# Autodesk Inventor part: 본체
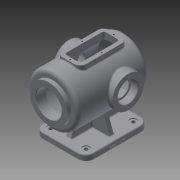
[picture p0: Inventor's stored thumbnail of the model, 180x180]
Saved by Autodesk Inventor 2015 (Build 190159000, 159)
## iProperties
Created: 2021-11
Part Number: 본체
Material: 일반
Document SubType Name: Modeling
Designer: G08
Density: 1 g/cm^3
Appearance: 기본값
Author: G08
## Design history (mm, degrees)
sketch "스케치1"
  geometry: L1 (65, -80)-(-65, -80); L2 (-65, -80)-(-65, 80); L3 (-65, 80)-(65, 80); L4 (65, 80)-(65, -80); L5 (65, -80)-(-65, 80); L6 (-65, -80)-(65, 80); 1 further point
  constraints: 12 end point, 2 midpoint, 2 parallel, 1 horizontal, 1 perpendicular
  dimensions: "d0" = 130 distance of L2.end L3.end; "d1" = 160 distance of L1.end L2.end
extrude "돌출1" new body sketch "스케치1" distance "d2" = 14; taper "d3" = 0 deg
sketch "스케치2"
  geometry: L1 (-65, 0)-(-65, 14) reference; L2 (-65, 14)-(65, 14) reference; L3 (65, 14)-(65, 0) reference; L4 (65, 0)-(-65, 0) reference; C1 r 65 at (0, 114); 1 further point
  constraints: 1 centre point
  dimensions: "d5" = 130 diameter of C1; "d6" = 114 distance from line of L4 C1.centre
extrude "돌출2" join sketch "스케치2" stored distance "d7" = 200; taper "d8" = 0 deg
sketch "스케치3"
  geometry: L1 (50, -7)-(-50, -7); L2 (-50, -7)-(-50, 7); L3 (-50, 7)-(50, 7); L4 (50, 7)-(50, -7); L5 (50, -7)-(-50, 7); L6 (-50, -7)-(50, 7); L7 (7, -60)-(-7, -60); L8 (-7, -60)-(-7, 60); L9 (-7, 60)-(7, 60); L10 (7, 60)-(7, -60); L11 (7, -60)-(-7, 60); L12 (-7, -60)-(7, 60); 1 further point
  constraints: 24 end point, 4 midpoint, 4 parallel, 2 horizontal, 2 perpendicular
  dimensions: "d9" = 14 distance of L8.end L9.end; "d10" = 14 distance of L3.end L1.start; "d11" = 120 distance of L9.end L7.start; "d12" = 100 distance of L2.end L3.end
extrude "돌출3" join sketch "스케치3" stored distance "d13" = 210; taper "d14" = 0 deg
sketch "스케치4"
  geometry: C1 r 65 at (0, 0) reference; C2 r 47.5 at (0, 0); 1 further point
  constraints: 1 centre point, 1 coincident
  dimensions: "d15" = 95 diameter of C2
extrude "돌출4" join sketch "스케치4" distance "d16" = 10; taper "d17" = 0 deg
sketch "스케치5"
  geometry: C1 r 47.5 at (0, 0) reference; 1 further point
hole "구멍1" sketch "스케치5" at (0, 0) diameter "d18" = 65; stored, may be unused: countersink angle "d22" = 90 deg, drill point angle "d24" = 0 deg; dims "d19" = 6, "d20" = 4, "d21" = 2, "d23" = 25
sketch "스케치6"
  geometry: C1 r 32.5 at (0, 0) reference; C2 r 55 at (0, 0); 1 further point
  constraints: 1 centre point, 1 coincident
  dimensions: "d25" = 110 diameter of C2
extrude "돌출5" cut sketch "스케치6" distance "d26" = 175; taper "d27" = 0 deg
sketch "스케치8"
  geometry: L1 (-80, 0)-(-80, 14) reference; L2 (-80, 14)-(-60, 14) reference; L3 (-60, 14)-(-60, 49) reference; L4 (-60, 49)-(-100, 49) reference; L5 (-100, 49)-(-100, 66.5) reference; L6 (-100, 66.5)-(-110, 66.5) reference; L7 (-110, 66.5)-(-110, 81.5) reference; L8 (-110, 81.5)-(-85, 81.5) reference; L9 (-85, 81.5)-(-85, 59) reference; L10 (-85, 59)-(90, 59) reference; L11 (90, 59)-(90, 169) reference; L12 (90, 169)-(-85, 169) reference; L13 (-85, 169)-(-85, 146.5) reference; L14 (-85, 146.5)-(-110, 146.5) reference; L15 (-110, 146.5)-(-110, 161.5) reference; L16 (-110, 161.5)-(-100, 161.5) reference; L17 (-100, 161.5)-(-100, 179) reference; L18 (-100, 179)-(100, 179) reference; L19 (100, 179)-(100, 49) reference; L20 (100, 49)-(60, 49) reference; L21 (60, 49)-(60, 14) reference; L22 (60, 14)-(80, 14) reference; L23 (80, 14)-(80, 0) reference; L24 (80, 0)-(-80, 0) reference; C1 r 21 at (17, 114); 1 further point
  constraints: 1 centre point
  dimensions: "d28" = 42 diameter of C1; "d29" = 127 distance from line of L15 C1.centre; "d30" = 114 distance from line of L24 C1.centre
extrude "돌출6" cut sketch "스케치8" stored distance "d31" = 175; taper "d32" = 0 deg
node "작업 평면3"
  node "작업 평면2"
sketch "스케치9"
  geometry: L1 (100, -65)-(100, 65) reference; L2 (-100, 65)-(-100, -65) reference; L3 (7, -41.533)-(-7, -41.533) reference; L4 (-7, -41.533)-(-7, -64.622) reference; L5 (-7, -64.622)-(-60, -64.622) reference; L6 (-60, -64.622)-(-60, -64.622) reference; L7 (-60, -64.622)-(-7, -64.622) reference; L8 (-7, -64.622)-(-7, -41.533) reference; L9 (-7, -41.533)-(7, -41.533) reference; L10 (7, -41.533)-(7, -64.622) reference; L11 (7, -64.622)-(60, -64.622) reference; L12 (60, -64.622)-(60, -64.622) reference; L13 (60, -64.622)-(7, -64.622) reference; L14 (7, -64.622)-(7, -41.533) reference; L15 (-80, -114)-(80, -114) reference; L16 (-80, -114)-(80, -114) reference; L17 (-80, -114)-(-80, -100) reference; L18 (80, -100)-(-80, -100) reference; L19 (80, -114)-(80, -100) reference; L20 (-110, 47.5)-(-110, -47.5) reference; C1 r 40 at (17, 0); 3 further points
  constraints: 1 centre point, 2 other
  dimensions: "d34" = 80 diameter of C1; "d35" = 114 distance from line of L15 C1.centre; "d36" = 127 distance from line of L20 C1.centre
extrude "돌출7" join sketch "스케치9" stored distance "d37" = 175; taper "d38" = 0 deg
sketch "스케치10"
  geometry: C1 r 40 at (0, 0) reference; C2 r 26 at (0, 0); 2 further points
  constraints: 1 centre point, 1 coincident, 1 other
  dimensions: "d39" = 52 diameter of C2
extrude "돌출8" cut sketch "스케치10" distance "d40" = 18; taper "d41" = 0 deg
node "작업 평면5"
  node "작업 평면4"
sketch "스케치11"
  geometry: L1 (-55, -85)-(-55, 90) reference; L2 (-65, -100)-(65, -100) reference; L3 (65, 100)-(-65, 100) reference; L4 (-47.5, -110)-(47.5, -110) reference; L5 (-65, -100)-(-65, 100) reference; L6 (65, -100)-(65, 100) reference; L7 (55, -85)-(55, 90) reference; L8 (30, -60)-(-30, -60); L9 (-30, -60)-(-30, 60); L10 (-30, 60)-(30, 60); L11 (30, 60)-(30, -60); L12 (30, -60)-(-30, 60); L13 (-30, -60)-(30, 60); L14 (75, 57)-(75, -23) reference; 2 further points
  constraints: 12 end point, 2 midpoint, 2 parallel, 1 horizontal, 1 perpendicular
  dimensions: "d43" = 60 distance of L9.end L10.end; "d44" = 120 distance of L8.end L9.end; "d45" = 50 distance between parallel lines of L4 L8; "d46" = 45 distance between parallel lines of L14 L11
extrude "돌출9" join sketch "스케치11" stored distance "d47" = 18; taper "d48" = 0 deg
sketch "스케치12"
  geometry: L1 (20, -50)-(-20, -50); L2 (-20, -50)-(-20, 50); L3 (-20, 50)-(20, 50); L4 (20, 50)-(20, -50); L5 (20, -50)-(-20, 50); L6 (-20, -50)-(20, 50); 1 further point
  constraints: 12 end point, 2 midpoint, 2 parallel, 1 horizontal, 1 perpendicular
  dimensions: "d49" = 40 distance of L2.end L3.end; "d50" = 100 distance of L1.end L2.end
extrude "돌출10" cut sketch "스케치12" distance "d51" = 30; taper "d52" = 0 deg
fillet "모깎기1" dims "d53" = 15
fillet "모깎기2" dims "d54" = 5
sketch "스케치13"
  geometry: 5 further points
  constraints: 2 horizontal alignment, 2 vertical alignment
  dimensions: "d55" = 25 distance of point (0, 0) point (-25, 0); "d56" = 50 distance of point (-25, 0) point (25, 0); "d57" = 110 distance of point (0, 55) point (0, -55); "d58" = 55 distance of point (0, 0) point (0, -55)
hole "구멍2" sketch "스케치13" at (-25, 0), (25, 0), (0, 55), (0, -55) diameter "d59" = 3.242; stored, may be unused: countersink angle "d63" = 90 deg, drill point angle "d65" = 118 deg; dims "d60" = 9, "d61" = 4, "d62" = 2, "d64" = 11
sketch "스케치14"
  geometry: L1 (0, 160)-(0, 0) reference; L2 (-31.658, 74.061)-(-31.658, 85.939); L3 (-31.658, 85.939)-(21.658, 85.939); L4 (21.658, 85.939)-(21.658, 74.061); L5 (21.658, 74.061)-(-31.658, 74.061); 2 further points
  constraints: 1 midpoint, 2 other
feature "엠보싱1" sketch "스케치14" dims "d68" = 0.5, "d69" = 0
sketch "스케치15"
  geometry: C1 r 26 at (0, 0) reference; 2 further points
  constraints: 1 horizontal alignment
  dimensions: "d70" = 32.5 distance of C1.centre point (-32.5, 0)
hole "구멍3" sketch "스케치15" at (-32.5, 0) diameter "d71" = 3.242; stored, may be unused: countersink angle "d75" = 90 deg, drill point angle "d77" = 118 deg; dims "d72" = 11, "d73" = 4, "d74" = 2, "d76" = 13
sketch "스케치16"
  geometry: C1 r 32.5 at (0, 0) reference; 2 further points
  constraints: 1 vertical alignment
  dimensions: "d81" = 40 distance of C1.centre point (0, 40)
hole "구멍4" sketch "스케치16" at (0, 40) diameter "d82" = 3.242; stored, may be unused: countersink angle "d86" = 90 deg, drill point angle "d88" = 118 deg; dims "d83" = 11, "d84" = 4, "d85" = 2, "d87" = 13
fillet "모깎기3" dims "d92" = 3
fillet "모깎기4" dims "d93" = 20
fillet "모깎기5" dims "d94" = 3
fillet "모깎기6" dims "d95" = 10
feature "면 기울기1" dims angle "d96" = 20 deg
feature "면 기울기2" dims angle "d97" = 20 deg
sketch "스케치18"
  geometry: C1 r 55 at (0, 0) reference; 1 further point
extrude "돌출11" join sketch "스케치18" distance "d100" = 20; taper "d101" = 0 deg
sketch "스케치17"
  geometry: L1 (-50, 184)-(-50, 169) reference; L2 (-50, 169)-(-85, 169) reference; L3 (-85, 81.5)-(-85, 59) reference; L4 (-110, 81.5)-(-85, 81.5) reference; L5 (-110, 146.5)-(-110, 152.379) reference; L6 (-110, 152.379)-(-97, 152.379) reference; L7 (-97, 152.379)-(-96.026, 154) reference; L8 (-96.026, 154)-(-97, 155.621) reference; L9 (-97, 155.621)-(-110, 155.621) reference; L10 (-110, 155.621)-(-110, 161.5) reference; L11 (-100, 66.5)-(-110, 66.5) reference; L12 (-100, 59)-(-100, 66.5) reference; L13 (-90, 179)-(-63, 179) reference; L14 (-60, 182)-(-60, 184) reference; L15 (-60, 184)-(-56.621, 184) reference; L16 (-56.621, 184)-(-56.621, 173) reference; L17 (-56.621, 173)-(-55, 172.026) reference; L18 (-55, 172.026)-(-53.379, 173) reference; L19 (-53.379, 173)-(-53.379, 184) reference; L20 (-53.379, 184)-(-50, 184) reference; L21 (70, 169)-(50, 169) reference; L22 (50, 169)-(50, 184) reference; L23 (50, 184)-(53.379, 184) reference; L24 (53.379, 184)-(53.379, 173) reference; L25 (53.379, 173)-(55, 172.026) reference; L26 (55, 172.026)-(56.621, 173) reference; L27 (56.621, 173)-(56.621, 184) reference; L28 (56.621, 184)-(60, 184) reference; L29 (60, 184)-(60, 182) reference; L30 (63, 179)-(100, 179) reference; L31 (100, 179)-(100, 49) reference; L32 (100, 49)-(47.261, 49) reference; L33 (47.261, 49)-(60, 14) reference; L34 (60, 14)-(77, 14) reference; L35 (80, 11)-(80, 0) reference; L36 (80, 0)-(-80, 0) reference; L37 (-80, 0)-(-80, 11) reference; L38 (-77, 14)-(-60, 14) reference; L39 (-60, 14)-(-47.261, 49) reference; L40 (-47.261, 49)-(-90, 49) reference; L41 (-100, 161.5)-(-100, 169) reference; L42 (-110, 161.5)-(-100, 161.5) reference; L43 (-110, 66.5)-(-110, 72.379) reference; L44 (-110, 72.379)-(-97, 72.379) reference; L45 (-97, 72.379)-(-96.026, 74) reference; L46 (-96.026, 74)-(-97, 75.621) reference; L47 (-97, 75.621)-(-110, 75.621) reference; L48 (-110, 75.621)-(-110, 81.5) reference; L49 (-85, 146.5)-(-110, 146.5) reference; L50 (-85, 169)-(-85, 146.5) reference; L51 (100, 49)-(100, 179) reference; L52 (100, 114)-(-110, 114); L53 (-85, 59)-(70, 59) reference; L54 (70, 59)-(70, 169) reference; A1 r 10 centre (-90, 59) between (-100, 59) and (-90, 49) reference; A2 r 3 centre (-63, 182) between (-63, 179) and (-60, 182) reference; A3 r 3 centre (63, 182) between (60, 182) and (63, 179) reference; A4 r 3 centre (77, 11) between (80, 11) and (77, 14) reference; A5 r 3 centre (-77, 11) between (-77, 14) and (-80, 11) reference; A6 r 10 centre (-90, 169) between (-90, 179) and (-100, 169) reference; A7 r 130.668 centre (0, 114) between (63.86, 0) and (79.982, 10.671); A8 r 100 centre (0, 114) between (100, 114) and (75.993, 179); 1 further point; 1 other entity
  constraints: 5 point on circle, 2 centre point, 2 end point, 2 point on line, 1 horizontal, 1 midpoint, 1 tangent, 2 other
  dimensions: "d99" = 100 radius of A8
revolve "회전1" sketch "스케치17" stored, may be unused: angle "d102" = 90 deg
sketch "스케치19"
  geometry: L1 (50, 169)-(50, 184) reference; L2 (50, 184)-(53.379, 184) reference; L3 (53.379, 184)-(53.379, 173) reference; L4 (53.379, 173)-(55, 172.026) reference; L5 (55, 172.026)-(56.621, 173) reference; L6 (56.621, 173)-(56.621, 184) reference; L7 (56.621, 184)-(60, 184) reference; L8 (60, 184)-(60, 182) reference; L9 (63, 179)-(75.993, 179) reference; L10 (75.993, 49)-(47.261, 49) reference; L11 (47.261, 49)-(60, 14) reference; L12 (60, 14)-(77, 14) reference; L13 (80, 11)-(80, 0) reference; L14 (80, 0)-(-80, 0) reference; L15 (-80, 0)-(-80, 11) reference; L16 (-77, 14)-(-60, 14) reference; L17 (-60, 14)-(-47.261, 49) reference; L18 (-47.261, 49)-(-90, 49) reference; L19 (-100, 59)-(-100, 66.5) reference; L20 (-100, 66.5)-(-110, 66.5) reference; L21 (-110, 66.5)-(-110, 72.379) reference; L22 (-110, 72.379)-(-97, 72.379) reference; L23 (-97, 72.379)-(-96.026, 74) reference; L24 (-96.026, 74)-(-97, 75.621) reference; L25 (-97, 75.621)-(-110, 75.621) reference; L26 (-110, 75.621)-(-110, 81.5) reference; L27 (-110, 81.5)-(-85, 81.5) reference; L28 (-85, 81.5)-(-85, 59) reference; L29 (-85, 59)-(70, 59) reference; L30 (70, 59)-(70, 169) reference; L31 (70, 169)-(50, 169) reference; L32 (-50, 184)-(-50, 169) reference; L33 (-50, 169)-(-85, 169) reference; L34 (-85, 169)-(-85, 146.5) reference; L35 (-85, 146.5)-(-110, 146.5) reference; L36 (-110, 146.5)-(-110, 152.379) reference; L37 (-110, 152.379)-(-97, 152.379) reference; L38 (-97, 152.379)-(-96.026, 154) reference; L39 (-96.026, 154)-(-97, 155.621) reference; L40 (-97, 155.621)-(-110, 155.621) reference; L41 (-110, 155.621)-(-110, 161.5) reference; L42 (-110, 161.5)-(-100, 161.5) reference; L43 (-100, 161.5)-(-100, 169) reference; L44 (-90, 179)-(-63, 179) reference; L45 (-60, 182)-(-60, 184) reference; L46 (-60, 184)-(-56.621, 184) reference; L47 (-56.621, 184)-(-56.621, 173) reference; L48 (-56.621, 173)-(-55, 172.026) reference; L49 (-55, 172.026)-(-53.379, 173) reference; L50 (-53.379, 173)-(-53.379, 184) reference; L51 (-53.379, 184)-(-50, 184) reference; L52 (0, 114)-(90, 114); L53 (45, 170.833)-(-45, 170.833) reference; L54 (0, 169)-(0, 114); L55 (71.239, 169)-(0, 169); A1 r 3 centre (63, 182) between (60, 182) and (63, 179) reference; A2 r 100 centre (0, 114) between (75.993, 49) and (75.993, 179) reference; A3 r 3 centre (77, 11) between (80, 11) and (77, 14) reference; A4 r 3 centre (-77, 11) between (-77, 14) and (-80, 11) reference; A5 r 10 centre (-90, 59) between (-100, 59) and (-90, 49) reference; A6 r 10 centre (-90, 169) between (-90, 179) and (-100, 169) reference; A7 r 3 centre (-63, 182) between (-63, 179) and (-60, 182) reference; A8 r 90 centre (0, 114) between (90, 114) and (71.239, 169); 3 further points
  constraints: 6 end point, 2 horizontal, 2 midpoint, 2 point on circle, 1 centre point, 1 point on line, 1 vertical
  dimensions: "d104" = 10 radial gap between concentric circles of A2 A8
revolve "회전2" sketch "스케치19" stored, may be unused: angle "d105" = 90 deg
fillet "모깎기7" dims "d106" = 10
fillet "모깎기8" dims "d107" = 3
fillet "모깎기9" dims "d108" = 3
chamfer "모따기1" distance "d109" = 1; stored, may be unused: second distance "d110" = 2, angle "d111" = 45 deg
fillet "모깎기10" dims "d112" = 3
fillet "모깎기11" dims "d113" = 3
sketch "스케치20"
  geometry: A1 r 17 centre (45, -60) between (45, -77) and (62, -60) reference; 1 further point
hole "구멍5" sketch "스케치20" at (45, -60) diameter "d114" = 9; stored, may be unused: countersink angle "d118" = 90 deg, drill point angle "d120" = 118 deg; dims "d115" = 11, "d116" = 4, "d117" = 2, "d119" = 14
sketch "스케치21"
  geometry: A1 r 17 centre (45, 60) between (62, 60) and (45, 77) reference; A2 r 17 centre (-45, 60) between (-45, 77) and (-62, 60) reference; A3 r 17 centre (-45, -60) between (-62, -60) and (-45, -77) reference; 1 further point
hole "구멍6" sketch "스케치21" at (45, 60), (-45, 60), (-45, -60) diameter "d121" = 9; stored, may be unused: countersink angle "d125" = 90 deg, drill point angle "d127" = 118 deg; dims "d122" = 11, "d123" = 4, "d124" = 2, "d126" = 14
sketch "스케치22"
  geometry: C1 r 4.5 at (-45, 60) reference; C2 r 4.5 at (45, 60) reference; C3 r 4.5 at (-45, -60) reference; C4 r 4.5 at (45, -60) reference; 1 further point
hole "구멍7" sketch "스케치22" at (45, -60), (45, 60), (-45, -60), (-45, 60) diameter "d128" = 18; stored, may be unused: countersink angle "d132" = 90 deg, drill point angle "d134" = 0 deg; dims "d129" = 11, "d130" = 4, "d131" = 2, "d133" = 2
fillet "모깎기12" dims "d135" = 0.3
node "솔리드1"
mirror "대칭1"
pattern_circular "원형 패턴1" dims angle "d79" = 360 deg
mirror "대칭2"
pattern_circular "원형 패턴2" dims angle "d90" = 360 deg
node "투영된 루프1"
node "투영된 루프2"
node "절단 모서리 투영1"
node "절단 모서리 투영2"
node "절단 모서리 투영3"
node "절단 모서리 투영4"
other parameters: "d42" = 5
